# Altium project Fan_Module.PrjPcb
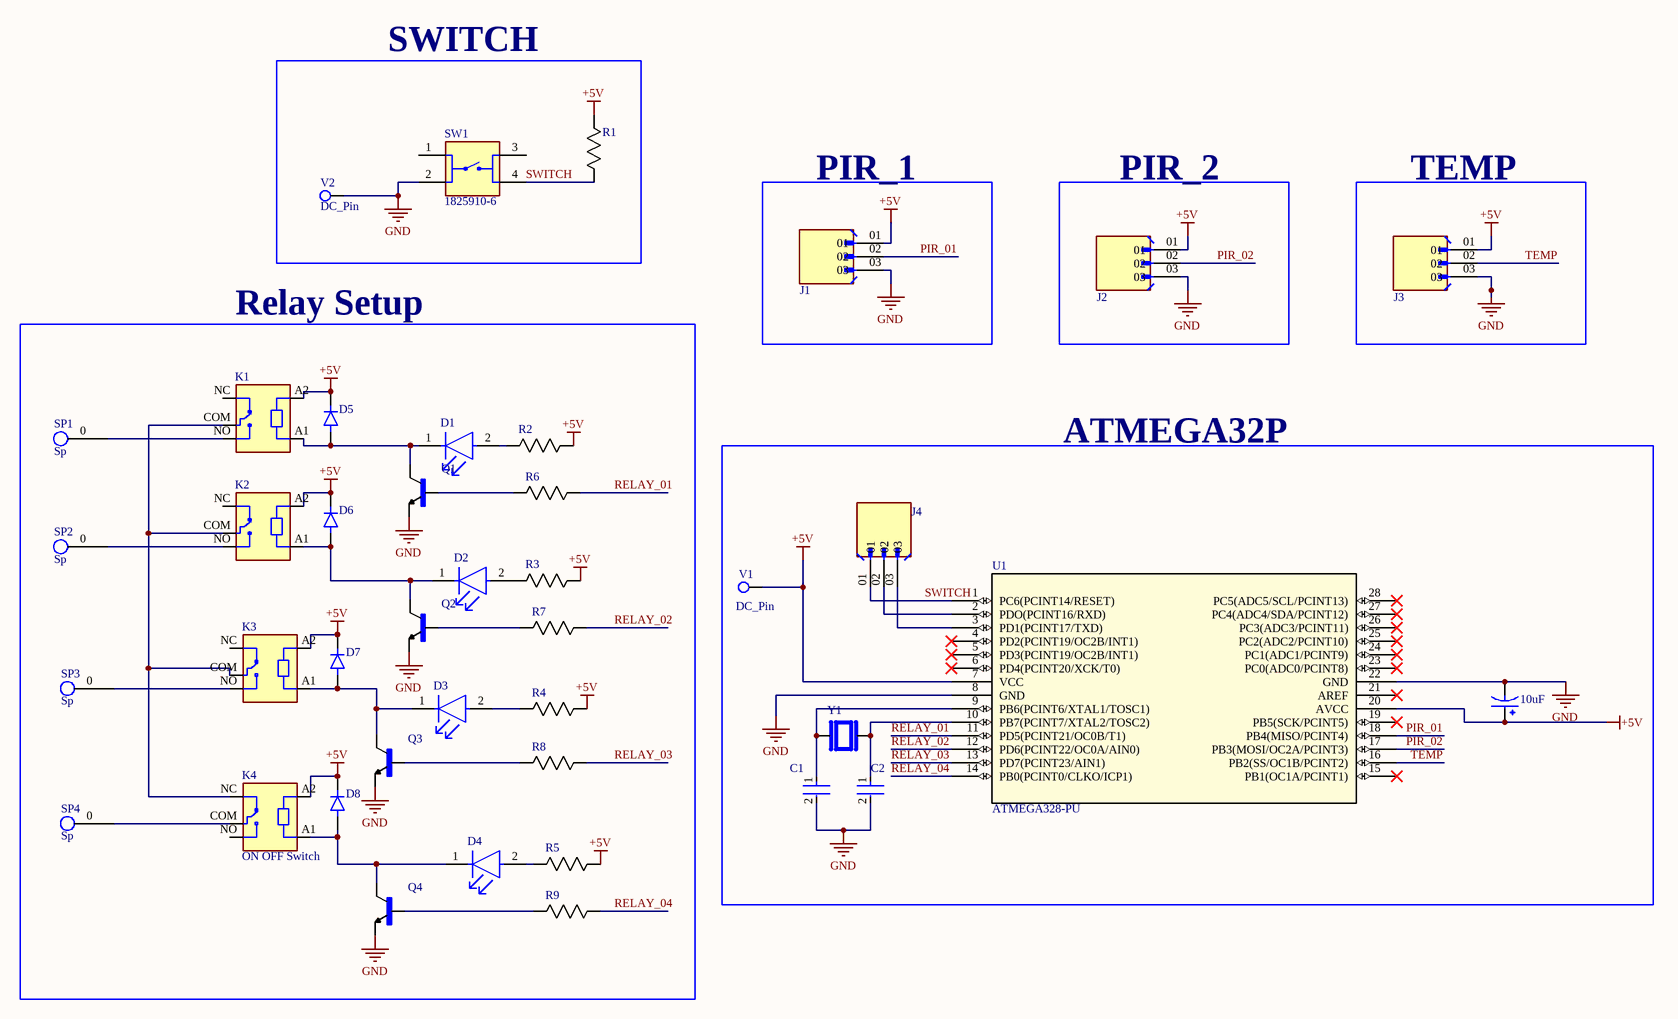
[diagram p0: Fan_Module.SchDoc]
1 sheet, 41 parts. Net scope: global (net labels, ports and power ports of the same name join across sheets).
Board file: Fan_Module.PcbDoc

## Sheet Fan_Module.SchDoc
size A3; SheetNumber: 1; SheetTotal: 1

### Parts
10uF  ECEA1HN100UI  [CAPPRD250W50D630H1120]  (value not drawn)
C1  RDE5C2A220J0M1H03A  [FP-RDE0M1-MFG]  (value not drawn)
C2  RDE5C2A220J0M1H03A  [FP-RDE0M1-MFG]  (value not drawn)
D1  TSFF5210  [FP-6_544-5258_09-4-MFG]  (value not drawn)
D2  TSFF5210  [FP-6_544-5258_09-4-MFG]  (value not drawn)
D3  TSFF5210  [FP-6_544-5258_09-4-MFG]  (value not drawn)
D4  TSFF5210  [FP-6_544-5258_09-4-MFG]  (value not drawn)
D5  1N4007G  [DIOAD1036W78L470D235]  (value not drawn)
D6  1N4007G  [DIOAD1036W78L470D235]  (value not drawn)
D7  1N4007G  [DIOAD1036W78L470D235]  (value not drawn)
D8  1N4007G  [DIOAD1036W78L470D235]  (value not drawn)
J1  68001-203HLF  [AMPHENOL_68001-203HLF]  (value not drawn)
J2  68001-203HLF  [AMPHENOL_68001-203HLF]  (value not drawn)
J3  68001-203HLF  [AMPHENOL_68001-203HLF]  (value not drawn)
J4  68001-203HLF  [AMPHENOL_68001-203HLF]  (value not drawn)
K1  SRD-05VDC-SL-C  [RELAY_SRD-05VDC-SL-C]  (value not drawn)
K2  SRD-05VDC-SL-C  [RELAY_SRD-05VDC-SL-C]  (value not drawn)
K3  SRD-05VDC-SL-C  [RELAY_SRD-05VDC-SL-C]  (value not drawn)
K4  ON OFF Switch  [RELAY_SRD-05VDC-SL-C]
Q1  2N3904  [TO92127P495H495-3]  (value not drawn)
Q2  2N3904  [TO92127P495H495-3]  (value not drawn)
Q3  2N3904  [TO92127P495H495-3]  (value not drawn)
Q4  2N3904  [TO92127P495H495-3]  (value not drawn)
R1  MFR-25FRF52-10K  [YAG_MF25_YAG]  (value not drawn)
R2  MFR-25FRF52-10K  [YAG_MF25_YAG]  (value not drawn)
R3  MFR-25FRF52-10K  [YAG_MF25_YAG]  (value not drawn)
R4  MFR-25FRF52-10K  [YAG_MF25_YAG]  (value not drawn)
R5  MFR-25FRF52-10K  [YAG_MF25_YAG]  (value not drawn)
R6  MFR-25FRF52-10K  [YAG_MF25_YAG]  (value not drawn)
R7  MFR-25FRF52-10K  [YAG_MF25_YAG]  (value not drawn)
R8  MFR-25FRF52-10K  [YAG_MF25_YAG]  (value not drawn)
R9  MFR-25FRF52-10K  [YAG_MF25_YAG]  (value not drawn)
SP1  Sp  [solderPoint]
SP2  Sp  [solderPoint]
SP3  Sp  [solderPoint]
SP4  Sp  [solderPoint]
SW1  1825910-6  [SW_1825910-6-4]
U1  ATMEGA328-PU  [28P3_SPDIP28_SP_MCH]
V1  DC_Pin  [DC_Pin]
V2  DC_Pin  [DC_Pin]
Y1  ABL-16.000MHZ-B2  [XTAL_HC49P488W46L1150T500H350]  (value not drawn)

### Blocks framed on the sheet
SWITCH: R1 SW1 V2
PIR_1: J1
PIR_2: J2
TEMP: J3
Relay Setup: D1-D8 K1-K4 Q1-Q4 R2-R9 SP1-SP4
ATMEGA32P: 10uF C1 C2 J4 U1 V1 Y1

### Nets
+5V: 10uF.P D5.C(K) D6.C(K) D7.C(K) D8.C(K) J1.01 J2.01 J3.01 K1.A2 K2.A2 K3.A2 K4.A2 R1.2 R2.2 R3.2 R4.2 R5.2 U1.7(VCC) U1.20(AVCC) V1.0
GND: 10uF.N C1.2 C2.2 J1.03 J2.03 J3.03 Q1.1(E) Q2.1(E) Q3.1(E) Q4.1(E) SW1.2 U1.8(GND) U1.22(GND) V2.0
PIR_01: J1.02 U1.18(PB4(MISO/PCINT4))
PIR_02: J2.02 U1.17(PB3(MOSI/OC2A/PCINT3))
RELAY_01: R6.2 U1.11(PD5(PCINT21/OC0B/T1))
RELAY_02: R7.2 U1.12(PD6(PCINT22/OC0A/AIN0))
RELAY_03: R8.2 U1.13(PD7(PCINT23/AIN1))
RELAY_04: R9.2 U1.14(PB0(PCINT0/CLKO/ICP1))
SWITCH: J4.01 R1.1 SW1.4 U1.1(PC6(PCINT14/RESET))
TEMP: J3.02 U1.16(PB2(SS/OC1B/PCINT2))
NetC1_1: C1.1 U1.9(PB6(PCINT6/XTAL1/TOSC1)) Y1.1
NetC2_1: C2.1 U1.10(PB7(PCINT7/XTAL2/TOSC2)) Y1.2
NetD1_1: D1.1(C) D5.A K1.A1 Q1.3(C)
NetD1_2: D1.2(A) R2.1
NetD2_1: D2.1(C) D6.A K2.A1 Q2.3(C)
NetD2_2: D2.2(A) R3.1
NetD3_1: D3.1(C) D7.A K3.A1 Q3.3(C)
NetD3_2: D3.2(A) R4.1
NetD4_1: D4.1(C) D8.A K4.A1 Q4.3(C)
NetD4_2: D4.2(A) R5.1
NetJ4_02: J4.02 U1.2(PDO(PCINT16/RXD))
NetJ4_03: J4.03 U1.3(PD1(PCINT17/TXD))
NetK1_COM: K1.COM K2.COM K3.COM K4.NC
NetK1_NO: K1.NO SP1.0
NetK2_NO: K2.NO SP2.0
NetK3_NO: K3.NO SP3.0
NetK4_COM: K4.COM SP4.0
NetQ1_2: Q1.2(B) R6.1
NetQ2_2: Q2.2(B) R7.1
NetQ3_2: Q3.2(B) R8.1
NetQ4_2: Q4.2(B) R9.1

Not connected (* = marked no-connect by the designer): K1 NC; K2 NC; K3 NC; K4 NO; SW1 1 3; U1 4(PD2(PCINT19/OC2B/INT1))* 5(PD3(PCINT19/OC2B/INT1))* 6(PD4(PCINT20/XCK/T0))* 15(PB1(OC1A/PCINT1))* 19(PB5(SCK/PCINT5))* 21(AREF)* 23(PC0(ADC0/PCINT8))* 24(PC1(ADC1/PCINT9))* 25(PC2(ADC2/PCINT10))* 26(PC3(ADC3/PCINT11))* 27(PC4(ADC4/SDA/PCINT12))* 28(PC5(ADC5/SCL/PCINT13))*

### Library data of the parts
10uF = ECEA1HN100UI: CAP ALUM 10UF 20% 50V RADIAL; MP: ECE-A1HN100UI; MF: Panasonic
C1 C2 = CMP-06035-022985-1: Ceramic Capacitor 22pF ±5% 100V C0G Radial; Lead Diameter: 0.5mm
D1-D4 = CMP-00030-41223146-1: TSFF5210 TSFF5210 IR LED, 870nm, T-1 3/4 (5mm) Through Hole package ¦ Siliconix / Vishay TSFF5210; Number of Elements: 1; Power Dissipation: 180W; Viewing Angle: 20°; Power Rating: 250mW; Test Current: 100mA; Forward Voltage: 1.5V; Lens Style: Circular, Colorless, Diffused, Round; Rise Time: 15ns; Reverse Voltage: 5V
D5-D8 = 1N4007G: 1A, 1000V, Standard Recovery Rectifier; MF: Taiwan Semiconductor
J1-J4 = 68001-203HLF: BergStik<sup>&reg;</sup>, Board to Board connector, Unshrouded vertical header, Through Hole, Single Row, , 3 Positions, 2.54 mm (0.100in) Pitch.; MF: Amphenol ICC
K1-K4 = SRD-05VDC-SL-C: 5V Trigger Relay Module For Arduino And Raspberry Pi 5V Trigger Relay Module For Arduino And Raspberry Pi; MF: Songle Relay
Q1-Q4 = 2N3904: TRANS NPN 40V 200MA TO92-3; MF: Rectron
R1-R9 = MFR-25FRF52-10K: No Description Available; Mfr_Name: Yageo
SP1-SP4 = soldPoint
SW1 = 1825910-6: Switch Push Button OFF (ON) SPST Round Button 0.05A 24VDC Momentary Contact PC Pins Thru-Hole; MF: TE Connectivity
U1 = ATMEGA328-PU: No Description Available; Mfr_Name: Microchip
Y1 = ABL-16.000MHZ-B2: HC/49US (AT49) MICROPROCESSOR CRYSTAL; MF: Abracon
